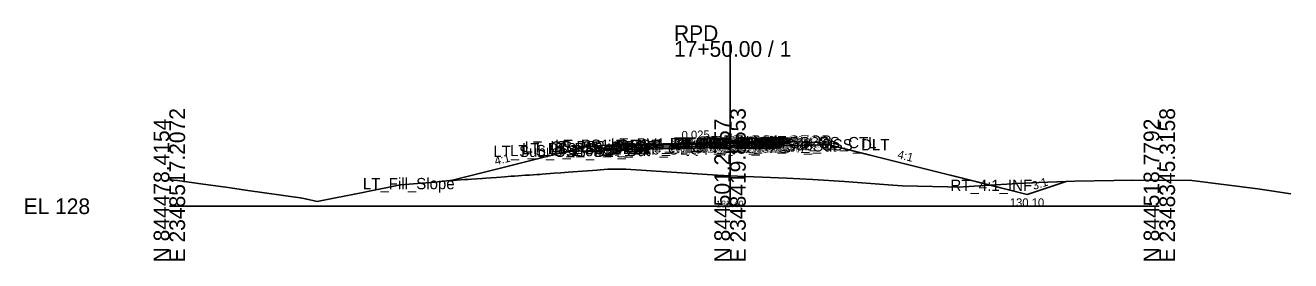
# Model space of a CAD drawing. Extents: x -26 to 2348536, y -510 to 844755.
# Drawn here: x -25.7 to 200, y 2490.3 to 2532.2 of the extents above; entities that cross this region are included whole.
import ezdxf

# ---------------------------------------------------------------- set-up
doc = ezdxf.new("R2010")
doc.units = 0
for name, color, linetype in [('Default', 7, 'Continuous'), ('Exist Cross Section Cell', 7, 'Continuous'), ('Exist XS Center Line Elevation Label', 7, 'Continuous'), ('Exist XS Ground Line', 7, 'Continuous'), ('Prop CMT Pvmt Course 1', 7, 'Continuous'), ('Prop CMT Pvmt Course 2', 7, 'Continuous'), ('Prop CMT Pvmt Course 3', 7, 'Continuous'), ('Prop CMT Pvmt Surface', 7, 'Continuous'), ('Prop CMT Pvmt Surface Shoulder', 7, 'Continuous'), ('Prop CMT Shld Paved Course 1', 7, 'Continuous'), ('Prop CMT Shld Paved Course 2', 7, 'Continuous'), ('Prop CMT Shld Paved Course 3', 7, 'Continuous'), ('Prop CMT Slope Grass', 7, 'Continuous'), ('Prop CMT Subgrade Earthwork', 7, 'Continuous'), ('Prop XS Ditch Standard Text', 7, 'Continuous'), ('Prop XS Earthwork Shape', 7, 'Continuous'), ('Prop XS SE Text', 7, 'Continuous'), ('Prop XS Side Slope Text', 7, 'Continuous'), ('Scratch_Level_0', 7, 'Continuous')]:
    doc.layers.add(name, color=color, linetype=linetype)

msp = doc.modelspace()

# ---------------------------------------------------------------- linework, layer by layer
at = {"layer": 'Exist Cross Section Cell'}
for p, q in [((100, 2500), (100, 2529.42)), ((0, 2500), (100, 2500)), ((100, 2500), (176.57, 2500))]:
    msp.add_line(p, q, dxfattribs=at)
at = {"layer": 'Exist XS Ground Line'}
msp.add_lwpolyline([(0, 2504.69), (1.43, 2504.6), (5.62, 2503.97), (10.47, 2503.33), (13.97, 2502.78), (23.36, 2501.51), (24.27, 2501.3), (26.39, 2500.86), (27.26, 2501.03), (29.32, 2501.42), (33.01, 2502.17), (41.25, 2503.82), (47.32, 2504.3), (50.05, 2504.56), (50.62, 2504.57), (51.22, 2504.62), (52.71, 2504.76), (53.25, 2504.77), (53.87, 2504.81), (55.79, 2504.94), (56.42, 2504.99), (58.36, 2505.14), (59.86, 2505.25), (60.95, 2505.33), (61.58, 2505.37), (63.53, 2505.51), (64.24, 2505.56), (65.56, 2505.67), (66.07, 2505.68), (66.48, 2505.72), (68.61, 2505.88), (69.83, 2505.98), (71.15, 2506.08), (71.98, 2506.14), (73.71, 2506.26), (75.5, 2506.39), (76.24, 2506.44), (78.19, 2506.58), (78.75, 2506.62), (80.19, 2506.61), (81.44, 2506.59), (82.28, 2506.53), (97.79, 2505.55), (100, 2505.4), (101.35, 2505.35), (110.16, 2504.98), (114.77, 2504.75), (120.43, 2504.41), (128.2, 2503.83), (130.7, 2503.64), (138.86, 2503.45), (140.97, 2503.41), (141.62, 2503.44), (151.25, 2504.03), (155.05, 2504.22), (161.52, 2504.48), (168.47, 2504.57), (171.79, 2504.64), (182.36, 2504.57), (194.14, 2503.08), (200, 2502.19)], dxfattribs=at)
at = {"layer": 'Prop CMT Pvmt Course 1'}
for p, q in [((100, 2511.42), (88, 2511.12)), ((88, 2510.87), (100, 2511.17)), ((88, 2511.12), (88, 2510.87)), ((100, 2511.42), (104, 2511.52)), ((100, 2511.17), (100, 2511.42)), ((100, 2511.17), (100, 2511.42)), ((100, 2511.17), (100, 2511.3)), ((100, 2511.3), (100, 2511.3)), ((100, 2511.3), (100, 2511.17)), ((100, 2511.17), (100, 2511.3)), ((100, 2511.3), (100, 2511.3)), ((100, 2511.3), (100, 2511.17)), ((104, 2511.27), (100, 2511.17)), ((100, 2511.17), (100, 2511.17)), ((100, 2511.17), (100, 2511.17)), ((104, 2511.52), (104, 2511.27))]:
    msp.add_line(p, q, dxfattribs=at)
at = {"layer": 'Prop CMT Pvmt Course 2'}
for p, q in [((100, 2511.17), (88, 2510.87)), ((88, 2510.87), (88, 2510.54)), ((88, 2510.54), (100, 2510.84)), ((100, 2511.17), (104, 2511.27)), ((100, 2510.84), (100, 2511.17)), ((100, 2510.84), (100, 2511.17)), ((104, 2510.94), (100, 2510.84)), ((104, 2511.27), (104, 2510.94))]:
    msp.add_line(p, q, dxfattribs=at)
at = {"layer": 'Prop CMT Pvmt Course 3'}
for p, q in [((100, 2510.84), (88, 2510.54)), ((88, 2510.54), (88, 2510.21)), ((88, 2510.21), (100, 2510.51)), ((100, 2510.84), (104, 2510.94)), ((100, 2510.51), (100, 2510.84)), ((100, 2510.51), (100, 2510.84)), ((104, 2510.61), (100, 2510.51)), ((104, 2510.94), (104, 2510.61))]:
    msp.add_line(p, q, dxfattribs=at)
at = {"layer": 'Prop CMT Pvmt Surface'}
for q in [(88, 2511.12), (104, 2511.52)]:
    msp.add_line((100, 2511.42), q, dxfattribs=at)
at = {"layer": 'Prop CMT Pvmt Surface Shoulder'}
for p, q in [((88, 2511.12), (78, 2510.87)), ((104, 2511.52), (108, 2511.62))]:
    msp.add_line(p, q, dxfattribs=at)
at = {"layer": 'Prop CMT Shld Paved Course 1'}
for p, q in [((78, 2510.87), (77.74, 2510.62)), ((77.74, 2510.62), (88, 2510.87)), ((88, 2511.12), (78, 2510.87)), ((88, 2510.87), (88, 2511.12)), ((104, 2511.52), (108, 2511.62)), ((104, 2511.27), (104, 2511.52)), ((108.24, 2511.38), (104, 2511.27)), ((108, 2511.62), (108.24, 2511.38))]:
    msp.add_line(p, q, dxfattribs=at)
at = {"layer": 'Prop CMT Shld Paved Course 2'}
for p, q in [((77.74, 2510.62), (77.4, 2510.28)), ((77.4, 2510.28), (88, 2510.54)), ((88, 2510.87), (77.74, 2510.62)), ((88, 2510.54), (88, 2510.87)), ((104, 2511.27), (108.24, 2511.38)), ((104, 2510.94), (104, 2511.27)), ((108.57, 2511.06), (104, 2510.94)), ((108.24, 2511.38), (108.57, 2511.06))]:
    msp.add_line(p, q, dxfattribs=at)
at = {"layer": 'Prop CMT Shld Paved Course 3'}
for p, q in [((76.9, 2510.26), (76.56, 2509.92)), ((76.56, 2509.92), (88, 2510.21)), ((77.4, 2510.28), (76.9, 2510.26)), ((88, 2510.54), (77.4, 2510.28)), ((88, 2510.21), (88, 2510.54)), ((104, 2510.94), (108.57, 2511.06)), ((104, 2510.61), (104, 2510.94)), ((109.39, 2510.74), (104, 2510.61)), ((108.57, 2511.06), (109.07, 2511.07)), ((109.07, 2511.07), (109.39, 2510.74))]:
    msp.add_line(p, q, dxfattribs=at)
at = {"layer": 'Prop CMT Slope Grass'}
for p, q in [((74, 2510.55), (50, 2504.55)), ((78, 2510.87), (74, 2510.55)), ((108, 2511.62), (116, 2511.34)), ((116, 2511.34), (152.98, 2502.1)), ((152.98, 2502.1), (159.94, 2504.42))]:
    msp.add_line(p, q, dxfattribs=at)
at = {"layer": 'Prop CMT Subgrade Earthwork'}
for p, q in [((76.56, 2509.92), (70.9, 2509.78)), ((88, 2510.21), (76.56, 2509.92)), ((100, 2510.51), (88, 2510.21)), ((100, 2510.51), (104, 2510.61)), ((104, 2510.61), (109.39, 2510.74)), ((109.39, 2510.74), (117.59, 2510.95))]:
    msp.add_line(p, q, dxfattribs=at)
at = {"layer": 'Prop XS Earthwork Shape'}
for points in [[(138.86, 2503.45), (140.97, 2503.41), (141.62, 2503.44), (146.44, 2503.73), (117.59, 2510.95), (109.39, 2510.74), (104, 2510.61), (100, 2510.51), (88, 2510.21), (76.56, 2509.92), (70.9, 2509.78), (50, 2504.55), (50.05, 2504.56), (50.62, 2504.57), (51.22, 2504.62), (52.71, 2504.76), (53.25, 2504.77), (53.87, 2504.81), (55.79, 2504.94), (56.42, 2504.99), (58.36, 2505.14), (59.86, 2505.25), (60.95, 2505.33), (61.58, 2505.37), (63.53, 2505.51), (64.24, 2505.56), (65.56, 2505.67), (66.07, 2505.68), (66.48, 2505.72), (68.61, 2505.88), (69.83, 2505.98), (71.15, 2506.08), (71.98, 2506.14), (73.71, 2506.26), (75.5, 2506.39), (76.24, 2506.44), (78.19, 2506.58), (78.75, 2506.62), (80.19, 2506.61), (81.44, 2506.59), (82.28, 2506.53), (97.79, 2505.55), (100, 2505.4), (101.35, 2505.35), (110.16, 2504.98), (114.77, 2504.75), (120.43, 2504.41), (128.2, 2503.83), (130.7, 2503.64)], [(155.05, 2504.22), (159.94, 2504.42), (152.98, 2502.1), (146.44, 2503.73), (151.25, 2504.03)]]:
    msp.add_lwpolyline(points, close=True, dxfattribs=at)

# ---------------------------------------------------------------- texts
at = {"layer": 'Default'}
msp.add_text('-', height=0.0001, dxfattribs=at).set_placement((0, 2500))
at = {"layer": 'Exist Cross Section Cell'}
for s, p in [('RPD', (90, 2529.42)), ('17+50.00 / 1', (90, 2526.62)), ('EL 128', (-26, 2498.6))]:
    msp.add_text(s, height=2.8, dxfattribs=at).set_placement(p)
for s, p in [('E 2348517.2072', (2.8, 2490)), ('E 2348419.8553', (102.8, 2490)), ('E 2348345.3158', (179.37, 2490)), ('N 844478.4154', (0, 2490)), ('N 844501.2757', (100, 2490)), ('N 844518.7792', (176.57, 2490))]:
    msp.add_text(s, height=2.8, rotation=90, dxfattribs=at).set_placement(p)
at = {"layer": 'Exist XS Center Line Elevation Label'}
msp.add_text('133.40', height=1.2, dxfattribs=at).set_placement((97.51, 2499.8))
at = {"layer": 'Prop XS Ditch Standard Text'}
msp.add_text('130.10', height=1.5, dxfattribs=at).set_placement((149.9, 2499.9))
at = {"layer": 'Prop XS SE Text'}
msp.add_text('0.025', height=1.5, rotation=1.4321, dxfattribs=at).set_placement((91.38, 2511.9))
at = {"layer": 'Prop XS Side Slope Text'}
for s, rotation, p in [('4:1', 345.9638, (129.77, 2508.57)), ('4:1', 14.0362, (58.2, 2507.3)), ('3:1', 17.8017, (154.16, 2502.88))]:
    msp.add_text(s, height=1.5, rotation=rotation, dxfattribs=at).set_placement(p)
at = {"layer": 'Scratch_Level_0'}
for s, p in [('LT_PV1_OEOT', (78.74, 2510.12)), ('RT_PV2_OEEOP', (89.26, 2510.17)), ('LT_PV2_OEEOP', (89.31, 2510.17)), ('RT_PV1_OEEOP', (89.83, 2510.3)), ('LT_PV1_OEEOP', (89.87, 2510.3)), ('RT_PV2_IEEOP', (89.91, 2510.17)), ('LT_PV2_IEEOP', (89.95, 2510.17)), ('RT_PV1_IEEOP', (90.47, 2510.3)), ('LT_PV1_IEEOP', (90.52, 2510.3)), ('PV2_PGL', (93.91, 2510.17)), ('RT_PV2_OEOT', (94.13, 2510.27)), ('RT_PV3_OEOT', (94.13, 2509.94)), ('PV1_PGL', (94.47, 2510.42)), ('RT_PV1_OEOT', (94.69, 2510.52)), ('RT_PS3_Shelf_Out', (95.01, 2510.07)), ('RT_PS2_OEOP', (98.43, 2510.38)), ('RT_PS1_OEOP', (98.76, 2510.62)), ('RT_PS3_OEOP', (98.76, 2510.06)), ('RT_Sub_OSS_DLT', (104.94, 2509.95)), ('RT_GS_OS_CTL', (105.32, 2510.34)), ('LT_Sub_OSS_DLT', (57.78, 2508.77)), ('LT_Sub_Trench_Out', (60.76, 2508.92)), ('LT_PS3_Shelf_Out', (62.89, 2509.26)), ('LT_GS_OS_CTL', (63.37, 2509.55)), ('LT_PS3_OEOP', (67.64, 2509.28)), ('LT_PS2_OEOP', (67.98, 2509.62)), ('LT_PS1_OEOP', (68.8, 2509.87)), ('LT_Sub_OEOT', (78.08, 2509.21)), ('LT_PV2_OEOT', (78.17, 2509.87)), ('LT_PV3_OEOT', (78.17, 2509.54)), ('RT_Sub_OEEOP', (89.17, 2509.51)), ('LT_Sub_OEEOP', (89.21, 2509.51)), ('RT_PV3_OEEOP', (89.26, 2509.84)), ('LT_PV3_OEEOP', (89.31, 2509.84)), ('RT_Sub_Trench_Out', (93.55, 2509.74)), ('RT_Sub_OEOT', (94.03, 2509.61)), ('LT_Fill_Slope', (34.52, 2503.04)), ('RT_4:1_INF', (139.32, 2502.73))]:
    msp.add_text(s, height=2, dxfattribs=at).set_placement(p)

doc.saveas('drawing.dxf')
